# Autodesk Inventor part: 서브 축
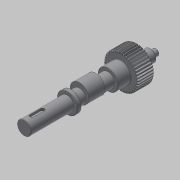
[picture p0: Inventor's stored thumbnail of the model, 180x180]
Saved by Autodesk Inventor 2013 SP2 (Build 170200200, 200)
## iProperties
Created: 2016-02
Part Number: 서브 축
Material: 일반
Document SubType Name: Modeling
Designer: mdu
Categories: <?xml version="1.0" encoding="UTF-16"?> <MemberInstance><Categories><FamilyTemplate><FamilyTemplateParameter ValueType="xs:double" Id="1" ObjectReferenceKey="da
Density: 1 g/cm^3
Mass: 506.173 g
Surface Area: 164.116 cm^2
Volume: 64.3986 cm^3
CustomPartVersion: 1
Author: mdu
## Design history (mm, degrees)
sketch "Sketch1"
  geometry: C1 r 21 at (0, 0)
  constraints: 1 centre point
  dimensions: "d0" = 42 diameter of C1 (= da_da)
extrude "Extrusion1" new body sketch "Sketch1" distance "d1" = 20 (= da_b); taper "d2" = 0 deg
workplane "Work Plane2"
feature "피치 지름" dims "d4" = 10, "d5" = 0
workplane "Work Plane8"
workplane "Work Plane9"
chamfer "모따기1" distance "d49" = 1; stored, may be unused: second distance "d50" = 2, angle "d51" = 45 deg
sketch "스케치3"
  geometry: C1 r 12.5 at (0, 0); 1 further point
  constraints: 1 centre point, 1 coincident
  dimensions: "d52" = 25 diameter of C1
extrude "돌출2" join sketch "스케치3" distance "d53" = 16; taper "d54" = 0 deg
sketch "스케치4"
  geometry: C1 r 8.5 at (0, 0); 1 further point
  constraints: 1 centre point, 1 coincident
  dimensions: "d55" = 17 diameter of C1
extrude "돌출3" join sketch "스케치4" distance "d56" = 103; taper "d57" = 0 deg
sketch "스케치5"
  geometry: C1 r 7.5 at (0, 0); 1 further point
  constraints: 1 centre point, 1 coincident
  dimensions: "d62" = 15 diameter of C1
extrude "돌출4" join sketch "스케치5" distance "d63" = 16; taper "d64" = 0 deg
sketch "스케치6"
  geometry: C1 r 4 at (0, 0); 1 further point
  constraints: 1 centre point, 1 coincident
  dimensions: "d65" = 8 diameter of C1
extrude "돌출5" join sketch "스케치6" distance "d66" = 7; taper "d67" = 0 deg
chamfer "모따기2" distance "d58" = 0.5; stored, may be unused: second distance "d59" = 2, angle "d60" = 45 deg
fillet "모깎기1" dims "d61" = 0.5
feature "스퍼 기어" dims "da_b" = 20, "da_d" = 40, "da_aw" = 31, "da_da" = 42, "da_df" = 37.5, "da_dw" = 40, angle "da_beta" = 0 deg, "da_lefttooth" = 0, "da_righttooth" = 0
node "작업 평면11"
sketch "스케치7"
  geometry: C1 r 8.5 at (0, 0) reference; C2 r 11.5 at (0, 3); 1 further point
  constraints: 1 centre point, 1 tangent, 1 vertical alignment
  dimensions: "d71" = 3 distance of C2.centre point (0, 0); "d72" = 23 diameter of C2 (derived)
extrude "돌출6" join sketch "스케치7" stored distance "d73" = 20; taper "d74" = 0 deg
node "작업 평면12"
sketch "스케치8"
  geometry: C1 r 12.5 at (0, 0) reference; 1 further point
extrude "돌출7" join sketch "스케치8" distance "d76" = 5; taper "d77" = 0 deg
chamfer "모따기3" distance "d78" = 0.5; stored, may be unused: second distance "d79" = 2, angle "d80" = 45 deg
sketch "스케치9"
  geometry: L1 (-8.5, 86)-(-8.5, 138.5) reference; L2 (-8, 139)-(8, 139) reference; L3 (0, 0)-(0, 139); L4 (-8.5, 115)-(0, 115); L5 (-8.5, 115)-(-8.5, 113.5); L6 (-7, 115)-(-8.5, 113.5)
  constraints: 8 end point, 4 point on line, 1 midpoint, 1 perpendicular
  dimensions: "d81" = 24 distance between parallel lines of L2 L4; "d82" = 45 deg angle of L6 L5; "d83" = 3 diameter of L5.end L4
revolve "회전1" sketch "스케치9" stored, may be unused: angle "d84" = 90 deg
sketch "스케치10"
  geometry: L1 (-8.5, 113.5)-(-7, 115) reference; L2 (-8.5, 116.5)-(-7, 115) reference; 2 further points
  constraints: 1 coincident
node "작업점1"
node "작업 평면14"
sketch "스케치11"
  geometry: L1 (8.5, 102.5)-(-8.5, 102.5) reference; L2 (0, 102.5)-(0, -36); L3 (-2.5, 93.5)-(-2.5, 80.5); L4 (2.5, 80.5)-(2.5, 93.5); L5 (-8, 103)-(8, 103) reference; A1 r 2.5 centre (0, 93.5) between (2.5, 93.5) and (-2.5, 93.5); A2 r 2.5 centre (0, 80.5) between (-2.5, 80.5) and (2.5, 80.5)
  constraints: 6 end point, 4 point on circle, 4 tangent, 2 centre point, 1 midpoint, 1 parallel, 1 perpendicular, 1 point on line, 1 vertical alignment
  dimensions: "d85" = 7 distance edge to line of A1 L5; "d86" = 18 dimension on A2 A1; "d87" = 5 distance between parallel lines of L3 L4
extrude "돌출8" cut sketch "스케치11" distance "d88" = 3; taper "d89" = 0 deg
body "Solid1"
sketch "Sketch2"
  geometry: C1 r 21 at (0, 0) reference; C2 r 20 at (0, 0)
  constraints: 1 centre point, 1 coincident
  dimensions: "d3" = 40 diameter of C2 (= da_dw)
body "Srf1"
other parameters: "d16" = 31 (= da_aw), "d17" = 0, "d34" = 4.5 deg (computed from da_z), "d39" = 0, "d41" = 0, "d43" = 31 (= da_aw), "d46" = 31 (= da_aw), "d47" = 0, "d48" = 0, "d68" = 25
